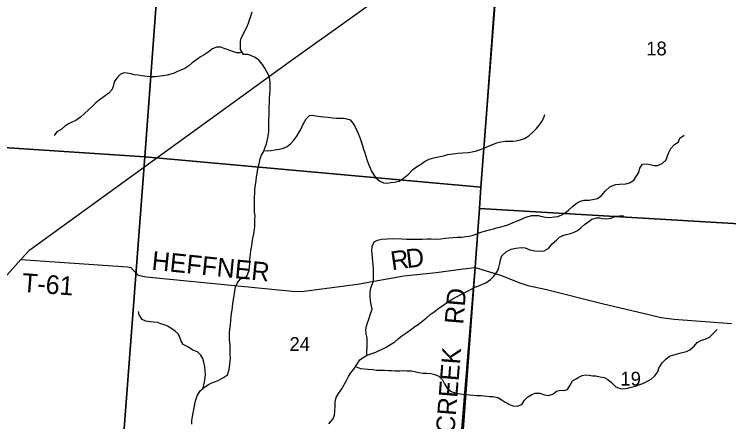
# Model space of a CAD drawing. Extents: x 0 to 42.5, y 0 to 22.
# Drawn here: x 4.623 to 5.708, y 16.976 to 17.595 of the extents above; entities that cross this region are included whole.
import ezdxf

# ---------------------------------------------------------------- set-up
doc = ezdxf.new("R2010")
doc.units = 0
for name, color, linetype in [('GM_X_Interchange_Ramps', 7, 'Continuous'), ('GM_X_Minor_River', 7, 'Continuous'), ('GM_X_Section', 7, 'Continuous'), ('GM_X_Section_Text', 7, 'Continuous'), ('GM_X_State_Route', 7, 'Continuous'), ('GM_X_Township', 7, 'Continuous'), ('GM_X_Township_Road', 7, 'Continuous'), ('GM_X_Township_Road_Text', 7, 'Continuous')]:
    doc.layers.add(name, color=color, linetype=linetype)

msp = doc.modelspace()

# ---------------------------------------------------------------- linework, layer by layer
at = {"layer": 'GM_X_Interchange_Ramps'}
msp.add_lwpolyline([(5.2142, 15.7986), (5.2389, 16.1139), (5.272, 16.5652), (5.3022, 16.9589), (5.3227, 17.2106), (5.363, 17.7533)], dxfattribs=at)
at = {"layer": 'GM_X_Minor_River'}
for points in [[(4.9801, 17.2109), (4.9805, 17.2173), (4.9805, 17.2227), (4.9814, 17.2308), (4.982, 17.2358), (4.9834, 17.2432), (4.9842, 17.2483), (4.9853, 17.2549), (4.9867, 17.2616), (4.9876, 17.268), (4.988, 17.2729), (4.9882, 17.2786), (4.9883, 17.2838), (4.9885, 17.2889), (4.9879, 17.2944), (4.9877, 17.3011), (4.9874, 17.3092), (4.9878, 17.3168), (4.988, 17.3235), (4.9884, 17.3286), (4.9893, 17.3358), (4.9901, 17.3424), (4.9907, 17.3478), (4.9915, 17.3525), (4.992, 17.3572), (4.9936, 17.3639), (4.9953, 17.3703), (4.9965, 17.3754), (4.9984, 17.3811), (5.0011, 17.3862), (5.004, 17.3932), (5.0057, 17.398), (5.0069, 17.4027), (5.0082, 17.4096), (5.0092, 17.417), (5.0094, 17.4225), (5.0094, 17.4291), (5.0096, 17.4358), (5.01, 17.4418), (5.01, 17.4489), (5.0099, 17.4538), (5.0103, 17.4608), (5.0106, 17.4673), (5.011, 17.4732), (5.0114, 17.4798), (5.0115, 17.4846), (5.0113, 17.4906), (5.0109, 17.4965), (5.0094, 17.5017), (5.0071, 17.5066), (5.0033, 17.5131), (4.9999, 17.5183), (4.9941, 17.5251), (4.9888, 17.5292), (4.9821, 17.5323), (4.9773, 17.5336), (4.9708, 17.5339), (4.9664, 17.5415), (4.9663, 17.5468), (4.9665, 17.5533), (4.9676, 17.5584), (4.9705, 17.5643), (4.9728, 17.5699), (4.9759, 17.5754), (4.9784, 17.5811), (4.9803, 17.5866), (4.982, 17.5917), (4.984, 17.5985)], [(4.9693, 17.5366), (4.966, 17.5364), (4.9609, 17.5364), (4.9544, 17.5385), (4.949, 17.5405), (4.9418, 17.543), (4.9364, 17.5447), (4.9299, 17.5448), (4.9236, 17.5422), (4.9175, 17.5373), (4.9111, 17.5333), (4.9056, 17.5302), (4.8998, 17.5262), (4.8929, 17.5209), (4.888, 17.5166), (4.882, 17.5127), (4.8755, 17.5097), (4.8707, 17.5078), (4.8658, 17.5056), (4.8604, 17.5041), (4.8548, 17.5026), (4.8487, 17.5015), (4.8367, 17.4999), (4.8313, 17.4997), (4.8248, 17.5002), (4.8166, 17.5014), (4.811, 17.5022), (4.8049, 17.503), (4.8, 17.5043), (4.7942, 17.5055), (4.7892, 17.5059), (4.7835, 17.5035), (4.7787, 17.4978), (4.7745, 17.492), (4.7731, 17.485), (4.7708, 17.48), (4.7666, 17.4751), (4.7574, 17.4687), (4.7515, 17.4642), (4.7467, 17.4603), (4.7419, 17.4559), (4.7354, 17.4499), (4.7291, 17.4435), (4.7231, 17.4386), (4.7162, 17.4337), (4.7112, 17.4315), (4.7051, 17.4283), (4.699, 17.4243), (4.6938, 17.42), (4.6875, 17.4161), (4.6835, 17.4108)], [(5.0018, 17.388), (5.0067, 17.3875), (5.0128, 17.3879), (5.0185, 17.389), (5.0254, 17.3901), (5.0317, 17.3915), (5.0373, 17.394), (5.0424, 17.3983), (5.0474, 17.4036), (5.0518, 17.41), (5.0555, 17.4159), (5.0584, 17.421), (5.0618, 17.428), (5.0659, 17.4359), (5.071, 17.4412), (5.076, 17.4417), (5.081, 17.4407), (5.0877, 17.4396), (5.093, 17.4389), (5.0995, 17.4385), (5.106, 17.4375), (5.1118, 17.4371), (5.1183, 17.4372), (5.123, 17.4372), (5.128, 17.4362), (5.1328, 17.4347), (5.1372, 17.4297), (5.1406, 17.424), (5.1433, 17.4186), (5.1452, 17.4139), (5.1478, 17.4076), (5.1497, 17.4015), (5.1516, 17.3958), (5.1534, 17.3899), (5.1551, 17.3842), (5.1568, 17.3792), (5.1583, 17.3745), (5.1606, 17.3674), (5.1627, 17.3625), (5.1655, 17.3564), (5.1684, 17.3516), (5.172, 17.3464), (5.1779, 17.3413), (5.1835, 17.3388), (5.1894, 17.3385), (5.1947, 17.3392), (5.1999, 17.3398), (5.2072, 17.3416), (5.2141, 17.3458), (5.2214, 17.3522), (5.2277, 17.3586), (5.234, 17.3631), (5.2398, 17.3668), (5.2461, 17.3712), (5.253, 17.3747), (5.2583, 17.3764), (5.2645, 17.3781), (5.2696, 17.379), (5.2748, 17.3801), (5.2815, 17.3817), (5.2897, 17.3828), (5.2966, 17.3837), (5.3042, 17.3846), (5.3121, 17.3849), (5.3182, 17.3862), (5.3247, 17.3877), (5.3312, 17.3893), (5.3362, 17.3914), (5.3431, 17.3948), (5.3492, 17.3972), (5.3557, 17.3994), (5.362, 17.4013), (5.3682, 17.402), (5.373, 17.402), (5.3795, 17.4023), (5.3852, 17.4026), (5.3919, 17.4041), (5.398, 17.4063), (5.4045, 17.4103), (5.4107, 17.4157), (5.4162, 17.4212), (5.4206, 17.4271), (5.4239, 17.432), (5.427, 17.4378), (5.4285, 17.4428)], [(5.5997, 17.3652), (5.607, 17.3685), (5.6129, 17.3736), (5.6145, 17.3786), (5.6168, 17.3837), (5.6199, 17.3909), (5.6256, 17.3969), (5.6317, 17.4014), (5.634, 17.4065), (5.6402, 17.4114)], [(5.1581, 17.0768), (5.159, 17.0975), (5.1587, 17.1038), (5.1571, 17.1099), (5.157, 17.1158), (5.1579, 17.1213), (5.1593, 17.1262), (5.1614, 17.1317), (5.1641, 17.1398), (5.1664, 17.1465), (5.1647, 17.1541), (5.1638, 17.1596), (5.1634, 17.1668), (5.1634, 17.1738), (5.1644, 17.179), (5.1661, 17.1837), (5.1684, 17.1896), (5.1686, 17.1955), (5.1686, 17.2006), (5.1683, 17.2072), (5.1677, 17.2146), (5.1673, 17.2194), (5.167, 17.2249), (5.1664, 17.2314), (5.166, 17.2363), (5.1662, 17.2424), (5.1695, 17.2492), (5.1747, 17.252), (5.1804, 17.2535), (5.189, 17.254), (5.1969, 17.2543), (5.2114, 17.2538), (5.219, 17.2536), (5.2246, 17.2536), (5.2324, 17.2533), (5.2378, 17.2533), (5.2428, 17.2536), (5.25, 17.2537), (5.256, 17.2537), (5.2627, 17.2535), (5.2707, 17.2538), (5.2774, 17.2549), (5.2827, 17.2552), (5.2891, 17.2559), (5.2957, 17.2565), (5.3019, 17.2566), (5.3088, 17.2575), (5.3137, 17.2582), (5.3185, 17.2591), (5.3243, 17.2608), (5.3292, 17.2629), (5.335, 17.2651), (5.3447, 17.2675), (5.3505, 17.2692), (5.3555, 17.2705), (5.3604, 17.2717), (5.3675, 17.2736), (5.3725, 17.2751), (5.3807, 17.2788), (5.3855, 17.2807), (5.3922, 17.2831), (5.3985, 17.2861), (5.4033, 17.2878), (5.4089, 17.2891), (5.4136, 17.2894), (5.4186, 17.2892), (5.4242, 17.2876), (5.4303, 17.2866), (5.436, 17.2862), (5.4435, 17.2871), (5.4486, 17.288), (5.4544, 17.2901), (5.4592, 17.2931), (5.4647, 17.2976), (5.4709, 17.303), (5.4776, 17.3083), (5.4831, 17.3111), (5.4887, 17.3124), (5.4961, 17.3126), (5.5013, 17.3135), (5.5086, 17.3153), (5.5149, 17.3196), (5.5203, 17.3261), (5.5272, 17.333), (5.5361, 17.3364), (5.5421, 17.3369), (5.5518, 17.3376), (5.5572, 17.3389), (5.5639, 17.3432), (5.5675, 17.3485), (5.5714, 17.3546), (5.5729, 17.361), (5.577, 17.367), (5.5829, 17.368), (5.5886, 17.3666), (5.5947, 17.365), (5.5997, 17.3652)], [(5.1006, 16.973), (5.1066, 16.9801), (5.1091, 16.986), (5.1095, 16.9919), (5.1102, 17.0008), (5.1104, 17.0067), (5.1116, 17.0128), (5.1154, 17.0192), (5.1202, 17.0262), (5.1233, 17.0317), (5.1273, 17.0387), (5.1304, 17.0447), (5.1335, 17.0498), (5.1385, 17.0561), (5.1433, 17.0632), (5.1477, 17.0701), (5.1529, 17.0738), (5.158, 17.0768), (5.1643, 17.0794), (5.1718, 17.0818), (5.177, 17.0843), (5.1827, 17.0869), (5.1877, 17.0895), (5.1959, 17.0944), (5.2009, 17.0976), (5.2061, 17.1021), (5.2116, 17.1064), (5.2193, 17.1119), (5.2266, 17.1172), (5.2314, 17.1209), (5.2364, 17.1241), (5.2421, 17.1283), (5.2484, 17.1337), (5.2546, 17.1388), (5.2605, 17.1429), (5.2657, 17.1469), (5.2722, 17.1516), (5.2774, 17.1553), (5.2841, 17.1599), (5.2904, 17.1638), (5.2973, 17.1674), (5.3023, 17.1698), (5.3093, 17.1733), (5.3143, 17.1762), (5.3214, 17.1799), (5.3285, 17.1827), (5.3342, 17.1851), (5.3392, 17.1872), (5.3463, 17.1921), (5.3511, 17.197), (5.3568, 17.2049), (5.3588, 17.2102), (5.3605, 17.2165), (5.3615, 17.222), (5.3636, 17.228), (5.3705, 17.2346), (5.3774, 17.238), (5.3848, 17.2399), (5.3931, 17.2406), (5.3988, 17.2403), (5.4059, 17.237), (5.4135, 17.2357), (5.4214, 17.2352), (5.4275, 17.2359), (5.4346, 17.2397), (5.4399, 17.2465), (5.4463, 17.2518), (5.4511, 17.2565), (5.4562, 17.2591), (5.4616, 17.2606), (5.4677, 17.2622), (5.4733, 17.2641), (5.4784, 17.2665), (5.4836, 17.2707), (5.4888, 17.2756), (5.4939, 17.2793), (5.5003, 17.2838), (5.5073, 17.2859), (5.5121, 17.2858), (5.5169, 17.2849), (5.5221, 17.2841), (5.5293, 17.2855), (5.5359, 17.2881), (5.542, 17.289), (5.5481, 17.2894)], [(4.8923, 16.9726), (4.8925, 16.9781), (4.8935, 16.9842), (4.8943, 16.99), (4.8958, 16.9972), (4.8976, 17.006), (4.8991, 17.0109), (4.9005, 17.0156), (4.9053, 17.023), (4.9123, 17.0292), (4.9179, 17.033), (4.9238, 17.0356), (4.9286, 17.0371), (4.9334, 17.0393), (4.9407, 17.0435), (4.9464, 17.0472), (4.9493, 17.0557), (4.9503, 17.0631), (4.9505, 17.0683), (4.9513, 17.0734), (4.9509, 17.0783), (4.9505, 17.0874), (4.9505, 17.0928), (4.9498, 17.1004), (4.9496, 17.1051), (4.9498, 17.1108), (4.9504, 17.1167), (4.951, 17.1232), (4.9516, 17.1298), (4.952, 17.1359), (4.9528, 17.1406), (4.9539, 17.1455), (4.9549, 17.1558), (4.9564, 17.1645), (4.9578, 17.1746), (4.9586, 17.181), (4.9611, 17.1865), (4.9661, 17.1929), (4.9708, 17.1954), (4.9762, 17.1969), (4.9795, 17.2061), (4.9801, 17.2109)], [(4.9091, 17.0264), (4.9099, 17.0281), (4.9112, 17.0342), (4.9126, 17.0429), (4.913, 17.0486), (4.9126, 17.0537), (4.9122, 17.0594), (4.9109, 17.0668), (4.9092, 17.072), (4.9059, 17.0773), (4.9012, 17.0823), (4.8939, 17.085), (4.8863, 17.09), (4.8794, 17.0933), (4.876, 17.0988), (4.8743, 17.1043), (4.872, 17.1093), (4.867, 17.1139), (4.8619, 17.1172), (4.8554, 17.1212), (4.8502, 17.1231), (4.8452, 17.1249), (4.8403, 17.127), (4.8345, 17.1276), (4.8297, 17.128), (4.8227, 17.129), (4.8169, 17.1315), (4.8124, 17.1386), (4.8114, 17.1435)], [(5.1413, 17.0603), (5.1488, 17.0571), (5.154, 17.0567), (5.1605, 17.0561), (5.1672, 17.0553), (5.1731, 17.0547), (5.1855, 17.0546), (5.1913, 17.0542), (5.196, 17.0539), (5.2012, 17.0533), (5.2085, 17.0537), (5.2138, 17.0538), (5.219, 17.0536), (5.2259, 17.0533), (5.2308, 17.0524), (5.2372, 17.0512), (5.244, 17.0502), (5.2496, 17.0498), (5.2557, 17.0493), (5.2616, 17.0481), (5.2679, 17.0452), (5.2733, 17.0399), (5.2761, 17.0336), (5.2803, 17.0271), (5.2866, 17.0219), (5.2943, 17.0196), (5.3, 17.0188), (5.3048, 17.018), (5.3096, 17.0174), (5.3147, 17.0172), (5.3203, 17.0166), (5.3251, 17.0163), (5.3318, 17.0161), (5.3367, 17.0155), (5.3446, 17.0147), (5.3497, 17.0148), (5.3572, 17.0131), (5.3622, 17.0102), (5.3686, 17.0058), (5.3751, 17.0023), (5.3803, 17.0004), (5.3874, 17.0001), (5.3937, 17.0024), (5.3979, 17.009), (5.4031, 17.0139), (5.4088, 17.0176), (5.4138, 17.0195), (5.4211, 17.0194), (5.4283, 17.0169), (5.4345, 17.0163), (5.441, 17.0182), (5.4463, 17.0225), (5.4523, 17.0242), (5.4578, 17.0237), (5.463, 17.0252), (5.4672, 17.0316), (5.4705, 17.0381), (5.4753, 17.0407), (5.4806, 17.0441), (5.4856, 17.0463), (5.4908, 17.0472), (5.4961, 17.0468), (5.5013, 17.046), (5.5063, 17.0458), (5.5129, 17.0446), (5.5187, 17.0436), (5.5244, 17.0402), (5.5298, 17.0356), (5.5364, 17.0294), (5.5431, 17.0267), (5.5483, 17.0263), (5.5542, 17.0272), (5.5598, 17.0285), (5.5678, 17.0309), (5.573, 17.0328), (5.5778, 17.0343), (5.5837, 17.0373), (5.5904, 17.0408), (5.5958, 17.0461), (5.6002, 17.0519), (5.6019, 17.0578), (5.6067, 17.0656), (5.6125, 17.0712), (5.6182, 17.0758), (5.6247, 17.0776), (5.6301, 17.0795), (5.6373, 17.0813), (5.6439, 17.0828), (5.6488, 17.0854), (5.6555, 17.0911), (5.6603, 17.0963), (5.6668, 17.1001), (5.6722, 17.1014), (5.6791, 17.1046), (5.685, 17.1108), (5.6906, 17.1163)], [(5.1582, 17.0872), (5.1582, 17.087)]]:
    msp.add_lwpolyline(points, dxfattribs=at)
at = {"layer": 'GM_X_Section'}
for points in [[(4.343, 17.9222), (4.8591, 17.8906), (4.821, 17.3784), (4.3076, 17.4121)], [(4.8591, 17.8906), (5.3703, 17.8445), (5.3699, 17.8309), (5.3314, 17.3322), (4.821, 17.3784)], [(5.3699, 17.8309), (5.869, 17.7911), (5.8269, 17.2708), (5.3293, 17.2998), (5.3314, 17.3322)], [(4.3076, 17.4121), (4.821, 17.3784), (4.7823, 16.8664), (4.2742, 16.8925)], [(5.3314, 17.3322), (5.3293, 17.2998), (5.2943, 16.8273), (5.2939, 16.8234), (4.7823, 16.8664), (4.821, 17.3784)], [(5.8269, 17.2708), (5.7883, 16.79), (5.2943, 16.8273), (5.3293, 17.2998)]]:
    msp.add_lwpolyline(points, close=True, dxfattribs=at)
at = {"layer": 'GM_X_State_Route'}
msp.add_lwpolyline([(3.7269, 15.9734), (4.1214, 16.5882), (4.1404, 16.6173), (4.307, 16.8691), (4.3916, 16.9605), (4.5415, 17.1208), (4.6327, 17.2223), (4.6462, 17.237), (5.0398, 17.5223), (5.3632, 17.7531)], dxfattribs=at)
at = {"layer": 'GM_X_Township'}
msp.add_lwpolyline([(5.2142, 15.7986), (5.2389, 16.1139), (5.272, 16.5652), (5.3022, 16.9589), (5.3227, 17.2106), (5.363, 17.7533), (5.387, 18.0749), (5.4438, 18.8389), (5.4812, 18.8357), (5.5392, 18.8313), (5.7041, 18.8187), (5.7765, 18.8132), (5.8742, 18.8063), (5.9445, 18.8008), (6.4254, 18.761), (6.6515, 18.7397)], dxfattribs=at)
at = {"layer": 'GM_X_Township_Road'}
msp.add_line((5.3228, 17.2104), (5.3632, 17.7531), dxfattribs=at)
for points in [[(4.6327, 17.2223), (4.7947, 17.2112), (4.8, 17.2102), (4.8039, 17.2058), (4.811, 17.1986), (4.8233, 17.1964), (5.0451, 17.1743), (5.0591, 17.1742), (5.1443, 17.1851), (5.2145, 17.1976), (5.2635, 17.203), (5.3044, 17.2084), (5.3178, 17.2098)], [(5.239, 16.1137), (5.2721, 16.5649), (5.3023, 16.9587), (5.3228, 17.2104)], [(5.3178, 17.2098), (5.3228, 17.2104), (5.3613, 17.1987), (5.3906, 17.1873), (5.4027, 17.1831), (5.4293, 17.1775), (5.5156, 17.1559), (5.5887, 17.1383), (5.6049, 17.1345), (5.6252, 17.1322), (5.7124, 17.1253)]]:
    msp.add_lwpolyline(points, dxfattribs=at)

# ---------------------------------------------------------------- texts
at = {"layer": 'GM_X_Section_Text'}
for s, p in [('18', (5.5827, 17.5324)), ('24', (5.0408, 17.0838)), ('19', (5.5435, 17.0311))]:
    msp.add_text(s, height=0.02093, rotation=0, dxfattribs=at).set_placement(p)
at = {"layer": 'GM_X_Township_Road_Text'}
for s, height, rotation, p in [('HEFFNER', 0.02841, 354.2585, (4.8306, 17.2071)), ('R', 0.0284, 8.0255, (5.1965, 17.2062)), ('D', 0.0284, 6.7952, (5.2194, 17.2094)), ('T-61', 0.02841, 355.7639, (4.6338, 17.1736)), ('RD', 0.02841, 85.0718, (5.3047, 17.1233)), ('SALTCREEK', 0.02841, 85.4491, (5.2838, 16.8627))]:
    msp.add_text(s, height=height, rotation=rotation, dxfattribs=at).set_placement(p)

doc.saveas('drawing.dxf')
